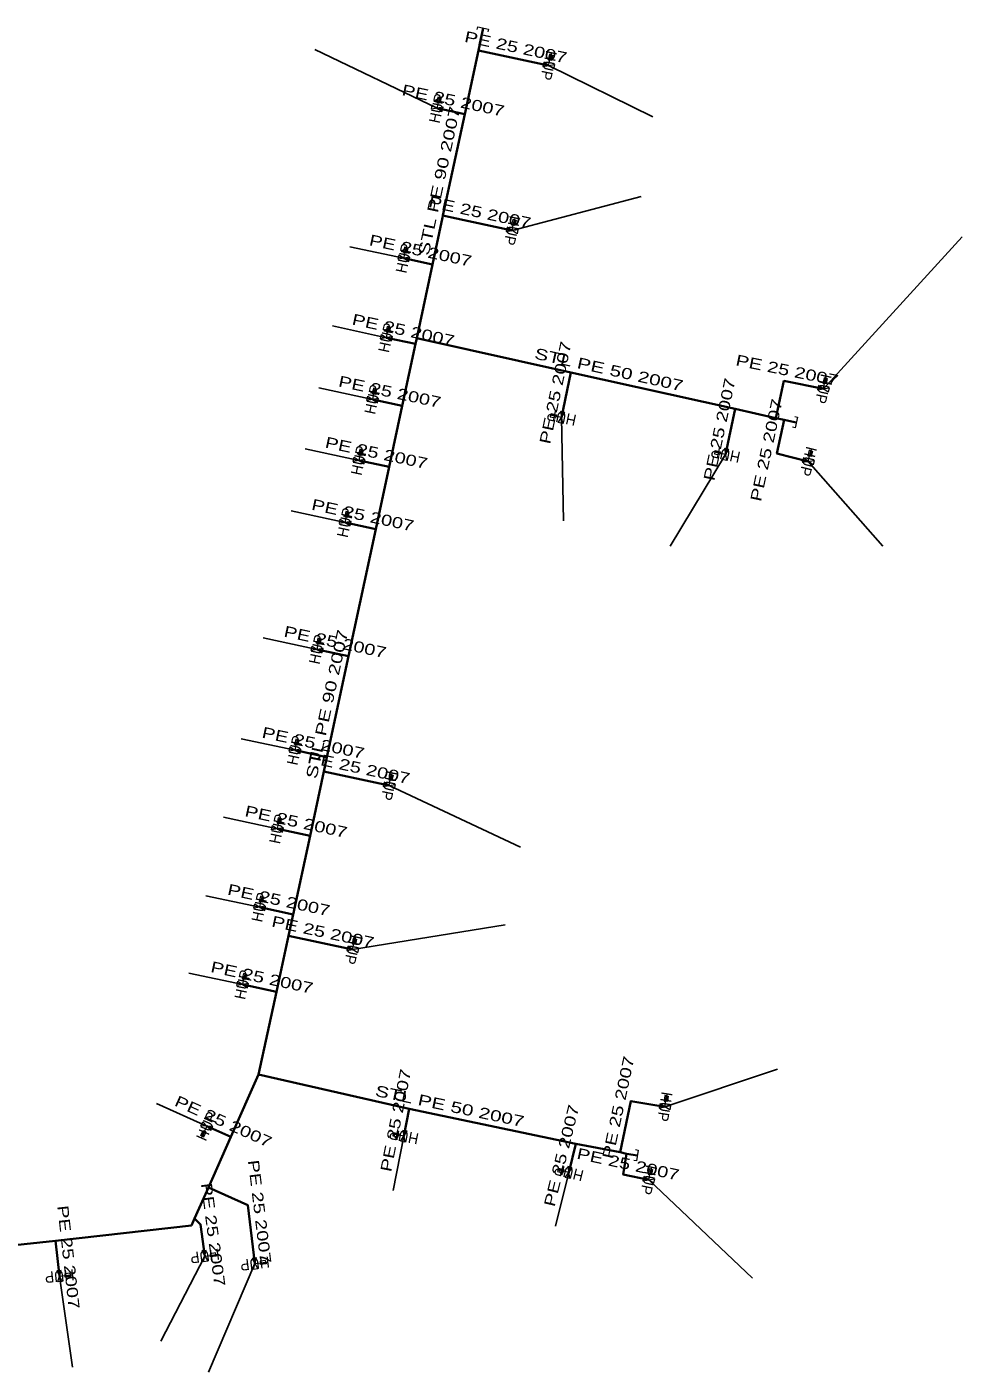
# Model space of a CAD drawing. Extents: x -737484 to -734496, y -1033882 to -1030666.
# Drawn here: x -735495.8 to -735411.1, y -1032104.6 to -1031982.7 of the extents above; entities that cross this region are included whole.
import ezdxf
from ezdxf.enums import TextEntityAlignment as Align

# ---------------------------------------------------------------- set-up
doc = ezdxf.new("R2010")
doc.units = 0
doc.header["$LTSCALE"] = 0.4
for name, color, linetype, lineweight in [('1', 7, 'Continuous', 13), ('22', 7, 'Continuous', 25), ('5', 7, 'Continuous', 35), ('7', 7, 'Continuous', 35)]:
    doc.layers.add(name, color=color, linetype=linetype, lineweight=lineweight)
doc.layers.add('2', color=7, linetype='Continuous')

msp = doc.modelspace()

# ---------------------------------------------------------------- linework, layer by layer
at = {"layer": '1'}
for p, q in [((-735448.387, -1031985.683), (-735448.314, -1031985.34)), ((-735448.58, -1031986.23), (-735448.476, -1031985.74)), ((-735458.477, -1031989.563), (-735458.404, -1031989.22)), ((-735458.67, -1031990.11), (-735458.566, -1031989.62)), ((-735451.89, -1032001.18), (-735451.786, -1032000.69)), ((-735451.697, -1032000.633), (-735451.624, -1032000.29)), ((-735461.68, -1032003.69), (-735461.576, -1032003.2)), ((-735461.487, -1032003.143), (-735461.414, -1032002.8)), ((-735463.26, -1032010.88), (-735463.156, -1032010.39)), ((-735463.067, -1032010.333), (-735462.994, -1032009.99)), ((-735423.517, -1032014.973), (-735423.444, -1032014.63)), ((-735464.51, -1032016.47), (-735464.406, -1032015.98)), ((-735464.317, -1032015.923), (-735464.244, -1032015.58)), ((-735423.71, -1032015.52), (-735423.606, -1032015.03)), ((-735447.966, -1032017.917), (-735448.309, -1032017.844)), ((-735447.42, -1032018.11), (-735447.909, -1032018.006)), ((-735465.74, -1032022), (-735465.636, -1032021.51)), ((-735465.547, -1032021.453), (-735465.474, -1032021.11)), ((-735433.116, -1032021.267), (-735433.459, -1032021.194)), ((-735432.57, -1032021.46), (-735433.059, -1032021.356)), ((-735425.08, -1032022.09), (-735424.959, -1032021.604)), ((-735424.868, -1032021.55), (-735424.783, -1032021.21)), ((-735466.807, -1032027.083), (-735466.734, -1032026.74)), ((-735467, -1032027.63), (-735466.896, -1032027.14)), ((-735469.54, -1032039.11), (-735469.436, -1032038.62)), ((-735469.347, -1032038.563), (-735469.274, -1032038.22)), ((-735471.347, -1032047.703), (-735471.274, -1032047.36)), ((-735471.54, -1032048.25), (-735471.436, -1032047.76)), ((-735463.02, -1032051.45), (-735462.916, -1032050.96)), ((-735462.827, -1032050.903), (-735462.754, -1032050.56)), ((-735473.13, -1032055.37), (-735473.026, -1032054.88)), ((-735472.937, -1032054.823), (-735472.864, -1032054.48)), ((-735474.74, -1032062.46), (-735474.636, -1032061.97)), ((-735474.547, -1032061.913), (-735474.474, -1032061.57)), ((-735466.33, -1032066.3), (-735466.226, -1032065.81)), ((-735466.137, -1032065.753), (-735466.064, -1032065.41)), ((-735476.28, -1032069.47), (-735476.176, -1032068.98)), ((-735476.087, -1032068.923), (-735476.014, -1032068.58)), ((-735438.06, -1032080.53), (-735437.981, -1032080.036)), ((-735437.895, -1032079.973), (-735437.841, -1032079.628)), ((-735479.832, -1032082.784), (-735479.974, -1032083.104)), ((-735479.53, -1032082.29), (-735479.733, -1032082.746)), ((-735462.24, -1032083.016), (-735462.583, -1032082.949)), ((-735461.69, -1032083.2), (-735462.18, -1032083.104)), ((-735447.299, -1032086.278), (-735447.639, -1032086.193)), ((-735446.76, -1032086.49), (-735447.245, -1032086.369)), ((-735439.52, -1032087.16), (-735439.416, -1032086.67)), ((-735439.327, -1032086.613), (-735439.254, -1032086.27)), ((-735479.71, -1032094.06), (-735479.214, -1032093.99)), ((-735479.13, -1032094.054), (-735478.783, -1032094.005)), ((-735475.18, -1032094.74), (-735474.683, -1032094.679)), ((-735474.6, -1032094.744), (-735474.252, -1032094.701)), ((-735492.87, -1032095.87), (-735492.372, -1032095.817)), ((-735492.29, -1032095.884), (-735491.942, -1032095.847))]:
    msp.add_line(p, q, dxfattribs=at)
for points in [[(-735455.051, -1031982.98), (-735454.999, -1031982.736), (-735454.02, -1031982.943), (-735454.072, -1031983.188)], [(-735426.3, -1032018.018), (-735426.056, -1032018.07), (-735426.263, -1032019.049), (-735426.508, -1032018.997)], [(-735440.718, -1032084.417), (-735440.471, -1032084.456), (-735440.628, -1032085.443), (-735440.875, -1032085.404)]]:
    msp.add_lwpolyline(points, dxfattribs=at)
for points in [[(-735448.372, -1031985.251), (-735448.518, -1031985.22), (-735448.622, -1031985.709), (-735448.476, -1031985.74)], [(-735448.372, -1031985.251), (-735448.225, -1031985.283), (-735448.329, -1031985.772), (-735448.476, -1031985.74)], [(-735448.343, -1031985.296), (-735448.27, -1031985.312), (-735448.358, -1031985.728), (-735448.432, -1031985.712)], [(-735448.049, -1031986.138), (-735448.132, -1031986.529), (-735449.027, -1031985.93), (-735449.11, -1031986.321)], [(-735458.462, -1031989.131), (-735458.608, -1031989.1), (-735458.712, -1031989.589), (-735458.566, -1031989.62)], [(-735458.462, -1031989.131), (-735458.315, -1031989.163), (-735458.419, -1031989.652), (-735458.566, -1031989.62)], [(-735458.433, -1031989.176), (-735458.36, -1031989.192), (-735458.448, -1031989.608), (-735458.522, -1031989.592)], [(-735459.2, -1031990.201), (-735459.117, -1031989.81), (-735458.222, -1031990.409), (-735458.139, -1031990.018)], [(-735451.682, -1032000.201), (-735451.828, -1032000.17), (-735451.932, -1032000.659), (-735451.786, -1032000.69)], [(-735451.682, -1032000.201), (-735451.535, -1032000.233), (-735451.639, -1032000.722), (-735451.786, -1032000.69)], [(-735451.359, -1032001.088), (-735451.442, -1032001.479), (-735452.337, -1032000.88), (-735452.42, -1032001.271)], [(-735451.653, -1032000.246), (-735451.58, -1032000.262), (-735451.668, -1032000.678), (-735451.742, -1032000.662)], [(-735462.21, -1032003.781), (-735462.127, -1032003.39), (-735461.232, -1032003.989), (-735461.149, -1032003.598)], [(-735461.472, -1032002.711), (-735461.618, -1032002.68), (-735461.722, -1032003.169), (-735461.576, -1032003.2)], [(-735461.472, -1032002.711), (-735461.325, -1032002.743), (-735461.429, -1032003.232), (-735461.576, -1032003.2)], [(-735461.443, -1032002.756), (-735461.37, -1032002.772), (-735461.458, -1032003.188), (-735461.532, -1032003.172)], [(-735463.052, -1032009.901), (-735463.198, -1032009.87), (-735463.302, -1032010.359), (-735463.156, -1032010.39)], [(-735463.052, -1032009.901), (-735462.905, -1032009.933), (-735463.009, -1032010.422), (-735463.156, -1032010.39)], [(-735463.023, -1032009.946), (-735462.95, -1032009.962), (-735463.038, -1032010.378), (-735463.112, -1032010.362)], [(-735463.79, -1032010.971), (-735463.707, -1032010.58), (-735462.812, -1032011.179), (-735462.729, -1032010.788)], [(-735423.502, -1032014.541), (-735423.648, -1032014.51), (-735423.752, -1032014.999), (-735423.606, -1032015.03)], [(-735423.502, -1032014.541), (-735423.355, -1032014.573), (-735423.459, -1032015.062), (-735423.606, -1032015.03)], [(-735423.473, -1032014.586), (-735423.4, -1032014.602), (-735423.488, -1032015.018), (-735423.562, -1032015.002)], [(-735464.302, -1032015.491), (-735464.448, -1032015.46), (-735464.552, -1032015.949), (-735464.406, -1032015.98)], [(-735464.302, -1032015.491), (-735464.155, -1032015.523), (-735464.259, -1032016.012), (-735464.406, -1032015.98)], [(-735464.273, -1032015.536), (-735464.2, -1032015.552), (-735464.288, -1032015.968), (-735464.362, -1032015.952)], [(-735423.179, -1032015.428), (-735423.262, -1032015.819), (-735424.157, -1032015.22), (-735424.24, -1032015.611)], [(-735465.04, -1032016.561), (-735464.957, -1032016.17), (-735464.062, -1032016.769), (-735463.979, -1032016.378)], [(-735448.398, -1032017.902), (-735448.429, -1032018.048), (-735447.94, -1032018.152), (-735447.909, -1032018.006)], [(-735448.398, -1032017.902), (-735448.366, -1032017.755), (-735447.877, -1032017.859), (-735447.909, -1032018.006)], [(-735448.353, -1032017.873), (-735448.337, -1032017.8), (-735447.921, -1032017.888), (-735447.937, -1032017.962)], [(-735447.328, -1032018.64), (-735447.719, -1032018.557), (-735447.12, -1032017.662), (-735447.511, -1032017.579)], [(-735432.478, -1032021.99), (-735432.869, -1032021.907), (-735432.27, -1032021.012), (-735432.661, -1032020.929)], [(-735466.27, -1032022.091), (-735466.187, -1032021.7), (-735465.292, -1032022.299), (-735465.209, -1032021.908)], [(-735465.532, -1032021.021), (-735465.678, -1032020.99), (-735465.782, -1032021.479), (-735465.636, -1032021.51)], [(-735465.532, -1032021.021), (-735465.385, -1032021.053), (-735465.489, -1032021.542), (-735465.636, -1032021.51)], [(-735465.503, -1032021.066), (-735465.43, -1032021.082), (-735465.518, -1032021.498), (-735465.592, -1032021.482)], [(-735433.548, -1032021.252), (-735433.579, -1032021.398), (-735433.09, -1032021.502), (-735433.059, -1032021.356)], [(-735433.548, -1032021.252), (-735433.516, -1032021.105), (-735433.027, -1032021.209), (-735433.059, -1032021.356)], [(-735433.503, -1032021.223), (-735433.487, -1032021.15), (-735433.071, -1032021.238), (-735433.087, -1032021.312)], [(-735424.546, -1032022.016), (-735424.643, -1032022.405), (-735425.516, -1032021.774), (-735425.613, -1032022.163)], [(-735424.838, -1032021.119), (-735424.983, -1032021.083), (-735425.104, -1032021.568), (-735424.959, -1032021.604)], [(-735424.838, -1032021.119), (-735424.692, -1032021.155), (-735424.813, -1032021.641), (-735424.959, -1032021.604)], [(-735424.811, -1032021.165), (-735424.738, -1032021.183), (-735424.841, -1032021.596), (-735424.914, -1032021.577)], [(-735466.792, -1032026.651), (-735466.938, -1032026.62), (-735467.042, -1032027.109), (-735466.896, -1032027.14)], [(-735466.792, -1032026.651), (-735466.645, -1032026.683), (-735466.749, -1032027.172), (-735466.896, -1032027.14)], [(-735466.763, -1032026.696), (-735466.69, -1032026.712), (-735466.778, -1032027.128), (-735466.852, -1032027.112)], [(-735467.53, -1032027.721), (-735467.447, -1032027.33), (-735466.552, -1032027.929), (-735466.469, -1032027.538)], [(-735470.07, -1032039.201), (-735469.987, -1032038.81), (-735469.092, -1032039.409), (-735469.009, -1032039.018)], [(-735469.332, -1032038.131), (-735469.478, -1032038.1), (-735469.582, -1032038.589), (-735469.436, -1032038.62)], [(-735469.332, -1032038.131), (-735469.185, -1032038.163), (-735469.289, -1032038.652), (-735469.436, -1032038.62)], [(-735469.303, -1032038.176), (-735469.23, -1032038.192), (-735469.318, -1032038.608), (-735469.392, -1032038.592)], [(-735471.332, -1032047.271), (-735471.478, -1032047.24), (-735471.582, -1032047.729), (-735471.436, -1032047.76)], [(-735471.332, -1032047.271), (-735471.185, -1032047.303), (-735471.289, -1032047.792), (-735471.436, -1032047.76)], [(-735471.303, -1032047.316), (-735471.23, -1032047.332), (-735471.318, -1032047.748), (-735471.392, -1032047.732)], [(-735472.07, -1032048.341), (-735471.987, -1032047.95), (-735471.092, -1032048.549), (-735471.009, -1032048.158)], [(-735462.489, -1032051.358), (-735462.572, -1032051.749), (-735463.467, -1032051.15), (-735463.55, -1032051.541)], [(-735462.812, -1032050.471), (-735462.958, -1032050.44), (-735463.062, -1032050.929), (-735462.916, -1032050.96)], [(-735462.812, -1032050.471), (-735462.665, -1032050.503), (-735462.769, -1032050.992), (-735462.916, -1032050.96)], [(-735462.783, -1032050.516), (-735462.71, -1032050.532), (-735462.798, -1032050.948), (-735462.872, -1032050.932)], [(-735472.922, -1032054.391), (-735473.068, -1032054.36), (-735473.172, -1032054.849), (-735473.026, -1032054.88)], [(-735472.922, -1032054.391), (-735472.775, -1032054.423), (-735472.879, -1032054.912), (-735473.026, -1032054.88)], [(-735472.893, -1032054.436), (-735472.82, -1032054.452), (-735472.908, -1032054.868), (-735472.982, -1032054.852)], [(-735473.66, -1032055.461), (-735473.577, -1032055.07), (-735472.682, -1032055.669), (-735472.599, -1032055.278)], [(-735475.27, -1032062.551), (-735475.187, -1032062.16), (-735474.292, -1032062.759), (-735474.209, -1032062.368)], [(-735474.532, -1032061.481), (-735474.678, -1032061.45), (-735474.782, -1032061.939), (-735474.636, -1032061.97)], [(-735474.532, -1032061.481), (-735474.385, -1032061.513), (-735474.489, -1032062.002), (-735474.636, -1032061.97)], [(-735474.503, -1032061.526), (-735474.43, -1032061.542), (-735474.518, -1032061.958), (-735474.592, -1032061.942)], [(-735465.799, -1032066.208), (-735465.882, -1032066.599), (-735466.777, -1032066), (-735466.86, -1032066.391)], [(-735466.122, -1032065.321), (-735466.268, -1032065.29), (-735466.372, -1032065.779), (-735466.226, -1032065.81)], [(-735466.122, -1032065.321), (-735465.975, -1032065.353), (-735466.079, -1032065.842), (-735466.226, -1032065.81)], [(-735466.093, -1032065.366), (-735466.02, -1032065.382), (-735466.108, -1032065.798), (-735466.182, -1032065.782)], [(-735476.81, -1032069.561), (-735476.727, -1032069.17), (-735475.832, -1032069.769), (-735475.749, -1032069.378)], [(-735476.072, -1032068.491), (-735476.218, -1032068.46), (-735476.322, -1032068.949), (-735476.176, -1032068.98)], [(-735476.072, -1032068.491), (-735475.925, -1032068.523), (-735476.029, -1032069.012), (-735476.176, -1032068.98)], [(-735476.043, -1032068.536), (-735475.97, -1032068.552), (-735476.058, -1032068.968), (-735476.132, -1032068.952)], [(-735437.534, -1032080.41), (-735437.597, -1032080.805), (-735438.522, -1032080.254), (-735438.585, -1032080.649)], [(-735437.903, -1032079.542), (-735438.051, -1032079.518), (-735438.129, -1032080.012), (-735437.981, -1032080.036)], [(-735437.903, -1032079.542), (-735437.755, -1032079.565), (-735437.833, -1032080.059), (-735437.981, -1032080.036)], [(-735437.872, -1032079.585), (-735437.798, -1032079.597), (-735437.865, -1032080.017), (-735437.939, -1032080.005)], [(-735479.936, -1032083.203), (-735480.073, -1032083.142), (-735479.87, -1032082.685), (-735479.733, -1032082.746)], [(-735480.068, -1032082.269), (-735479.905, -1032081.903), (-735479.154, -1032082.676), (-735478.991, -1032082.31)], [(-735479.955, -1032083.153), (-735480.023, -1032083.123), (-735479.85, -1032082.735), (-735479.782, -1032082.765)], [(-735479.936, -1032083.203), (-735479.799, -1032083.264), (-735479.596, -1032082.807), (-735479.733, -1032082.746)], [(-735462.671, -1032083.009), (-735462.7, -1032083.156), (-735462.209, -1032083.251), (-735462.18, -1032083.104)], [(-735462.671, -1032083.009), (-735462.643, -1032082.861), (-735462.152, -1032082.957), (-735462.18, -1032083.104)], [(-735462.627, -1032082.98), (-735462.612, -1032082.906), (-735462.195, -1032082.987), (-735462.21, -1032083.061)], [(-735461.589, -1032083.728), (-735461.981, -1032083.652), (-735461.398, -1032082.747), (-735461.79, -1032082.671)], [(-735447.73, -1032086.248), (-735447.766, -1032086.393), (-735447.281, -1032086.514), (-735447.245, -1032086.369)], [(-735447.73, -1032086.248), (-735447.694, -1032086.102), (-735447.208, -1032086.223), (-735447.245, -1032086.369)], [(-735447.684, -1032086.221), (-735447.666, -1032086.148), (-735447.253, -1032086.251), (-735447.272, -1032086.324)], [(-735446.686, -1032087.023), (-735447.075, -1032086.926), (-735446.444, -1032086.053), (-735446.833, -1032085.956)], [(-735439.312, -1032086.181), (-735439.458, -1032086.15), (-735439.562, -1032086.639), (-735439.416, -1032086.67)], [(-735439.312, -1032086.181), (-735439.165, -1032086.213), (-735439.269, -1032086.702), (-735439.416, -1032086.67)], [(-735439.283, -1032086.226), (-735439.21, -1032086.242), (-735439.298, -1032086.658), (-735439.372, -1032086.642)], [(-735438.989, -1032087.068), (-735439.072, -1032087.459), (-735439.967, -1032086.86), (-735440.05, -1032087.251)], [(-735479.442, -1032094.527), (-735479.838, -1032094.582), (-735479.581, -1032093.537), (-735479.977, -1032093.592)], [(-735478.719, -1032093.92), (-735478.74, -1032093.772), (-735479.235, -1032093.841), (-735479.214, -1032093.99)], [(-735478.719, -1032093.92), (-735478.698, -1032094.069), (-735479.193, -1032094.138), (-735479.214, -1032093.99)], [(-735478.752, -1032093.962), (-735478.741, -1032094.037), (-735479.162, -1032094.096), (-735479.173, -1032094.021)], [(-735474.92, -1032095.211), (-735475.317, -1032095.26), (-735475.042, -1032094.219), (-735475.439, -1032094.268)], [(-735474.187, -1032094.618), (-735474.205, -1032094.469), (-735474.702, -1032094.53), (-735474.683, -1032094.679)], [(-735474.187, -1032094.618), (-735474.169, -1032094.767), (-735474.665, -1032094.827), (-735474.683, -1032094.679)], [(-735474.22, -1032094.659), (-735474.211, -1032094.733), (-735474.633, -1032094.785), (-735474.642, -1032094.711)], [(-735492.618, -1032096.346), (-735493.016, -1032096.388), (-735492.723, -1032095.351), (-735493.121, -1032095.393)], [(-735491.875, -1032095.765), (-735491.891, -1032095.616), (-735492.388, -1032095.668), (-735492.372, -1032095.817)], [(-735491.875, -1032095.765), (-735491.859, -1032095.914), (-735492.357, -1032095.966), (-735492.372, -1032095.817)], [(-735491.909, -1032095.806), (-735491.901, -1032095.88), (-735492.324, -1032095.925), (-735492.332, -1032095.85)]]:
    msp.add_lwpolyline(points, close=True, dxfattribs=at)
at = {"layer": '22'}
for p, q in [((-735458.67, -1031990.11), (-735469.76, -1031984.772)), ((-735448.58, -1031986.23), (-735439.156, -1031990.889)), ((-735451.89, -1032001.18), (-735440.211, -1031998.101)), ((-735461.68, -1032003.69), (-735466.571, -1032002.651)), ((-735423.71, -1032015.52), (-735411.147, -1032001.753)), ((-735463.26, -1032010.88), (-735468.147, -1032009.821)), ((-735464.51, -1032016.47), (-735469.401, -1032015.43)), ((-735447.42, -1032018.11), (-735447.247, -1032027.476)), ((-735465.74, -1032022), (-735470.63, -1032020.957)), ((-735432.57, -1032021.46), (-735437.573, -1032029.763)), ((-735425.08, -1032022.09), (-735418.329, -1032029.757)), ((-735467, -1032027.63), (-735471.887, -1032026.572)), ((-735469.54, -1032039.11), (-735474.429, -1032038.064)), ((-735471.54, -1032048.25), (-735476.432, -1032047.217)), ((-735463.02, -1032051.45), (-735451.117, -1032057.027)), ((-735473.13, -1032055.37), (-735478.016, -1032054.31)), ((-735474.74, -1032062.46), (-735479.629, -1032061.415)), ((-735466.33, -1032066.3), (-735452.524, -1032064.063)), ((-735476.28, -1032069.47), (-735481.168, -1032068.419)), ((-735438.06, -1032080.53), (-735427.871, -1032077.12)), ((-735479.53, -1032082.29), (-735484.09, -1032080.24)), ((-735461.69, -1032083.2), (-735462.659, -1032088.105)), ((-735446.76, -1032086.49), (-735447.959, -1032091.344)), ((-735439.52, -1032087.16), (-735430.13, -1032096.042)), ((-735479.71, -1032094.06), (-735483.706, -1032101.756)), ((-735475.18, -1032094.74), (-735479.389, -1032104.562)), ((-735492.87, -1032095.87), (-735491.691, -1032104.13))]:
    msp.add_line(p, q, dxfattribs=at)
at = {"layer": '5'}
for points in [[(-735460.52, -1032010.94), (-735459.09, -1032004.24), (-735458.186, -1032000), (-735458.15, -1031999.83), (-735456.18, -1031990.64), (-735454.94, -1031984.87), (-735454.51, -1031982.84)], [(-735474.86, -1032077.61), (-735473.21, -1032070.13), (-735472.12, -1032065.06), (-735471.7, -1032063.11), (-735470.18, -1032056.01), (-735468.93, -1032050.18), (-735468.65, -1032048.86), (-735466.69, -1032039.72), (-735464.23, -1032028.23), (-735463.02, -1032022.58), (-735461.83, -1032017.04), (-735460.63, -1032011.45), (-735460.52, -1032010.94)], [(-735460.52, -1032010.94), (-735446.56, -1032014.03), (-735431.7, -1032017.33), (-735428, -1032018.17), (-735427.26, -1032018.32), (-735426.16, -1032018.56)], [(-735549.56, -1032088.85), (-735544.29, -1032089.97), (-735529.36, -1032093.16), (-735520.87, -1032094.93), (-735520.17, -1032095.11), (-735514.68, -1032094.87), (-735507.5, -1032094.15), (-735500.34, -1032093.43), (-735493.23, -1032092.66), (-735480.93, -1032091.29), (-735480.65, -1032090.65), (-735479.39, -1032087.84), (-735477.35, -1032083.27), (-735474.86, -1032077.61)], [(-735474.86, -1032077.61), (-735461.2, -1032080.72), (-735446.12, -1032083.9), (-735442.11, -1032084.63), (-735441.54, -1032084.8), (-735440.55, -1032084.95)]]:
    msp.add_lwpolyline(points, dxfattribs=at)
at = {"layer": '7'}
for p, q in [((-735454.94, -1031984.87), (-735448.58, -1031986.23)), ((-735456.18, -1031990.64), (-735458.67, -1031990.11)), ((-735459.09, -1032004.24), (-735461.68, -1032003.69)), ((-735460.63, -1032011.45), (-735463.26, -1032010.88)), ((-735446.56, -1032014.03), (-735447.42, -1032018.11)), ((-735461.83, -1032017.04), (-735464.51, -1032016.47)), ((-735431.7, -1032017.33), (-735432.57, -1032021.46)), ((-735463.02, -1032022.58), (-735465.74, -1032022)), ((-735464.23, -1032028.23), (-735467, -1032027.63)), ((-735466.69, -1032039.72), (-735469.54, -1032039.11)), ((-735468.65, -1032048.86), (-735471.54, -1032048.25)), ((-735468.93, -1032050.18), (-735463.02, -1032051.45)), ((-735470.18, -1032056.01), (-735473.13, -1032055.37)), ((-735471.7, -1032063.11), (-735474.74, -1032062.46)), ((-735472.12, -1032065.06), (-735466.33, -1032066.3)), ((-735473.21, -1032070.13), (-735476.28, -1032069.47)), ((-735461.2, -1032080.72), (-735461.69, -1032083.2)), ((-735477.35, -1032083.27), (-735479.53, -1032082.29)), ((-735446.12, -1032083.9), (-735446.76, -1032086.49)), ((-735493.23, -1032092.66), (-735492.87, -1032095.87))]:
    msp.add_line(p, q, dxfattribs=at)
for points in [[(-735458.15, -1031999.83), (-735457.361, -1032000), (-735451.89, -1032001.18)], [(-735428, -1032018.17), (-735427.28, -1032014.79), (-735423.71, -1032015.52)], [(-735427.26, -1032018.32), (-735427.91, -1032021.37), (-735425.08, -1032022.09)], [(-735442.11, -1032084.63), (-735441.13, -1032080.02), (-735438.06, -1032080.53)], [(-735441.54, -1032084.8), (-735441.83, -1032086.66), (-735439.52, -1032087.16)], [(-735479.39, -1032087.84), (-735475.83, -1032089.43), (-735475.18, -1032094.74)], [(-735480.65, -1032090.65), (-735480.09, -1032091.19), (-735479.71, -1032094.06)]]:
    msp.add_lwpolyline(points, dxfattribs=at)

# ---------------------------------------------------------------- texts
at = {"layer": '2', "width": 0.95}
for rotation, p in [(258, (-735449.0688, -1031986.1255)), (78, (-735458.1802, -1031990.2135)), (258, (-735452.3788, -1032001.0755)), (78, (-735461.1902, -1032003.7935)), (78, (-735462.7702, -1032010.9835)), (258, (-735424.1988, -1032015.4155)), (78, (-735464.0202, -1032016.5735)), (168, (-735447.3155, -1032017.6202)), (78, (-735465.2502, -1032022.1035)), (168, (-735432.4655, -1032020.9702)), (256, (-735425.565, -1032021.9685)), (78, (-735466.5102, -1032027.7335)), (78, (-735469.0502, -1032039.2135)), (78, (-735471.0502, -1032048.3535)), (258, (-735463.5088, -1032051.3455)), (78, (-735472.6402, -1032055.4735)), (78, (-735474.2502, -1032062.5635)), (258, (-735466.8188, -1032066.1955)), (78, (-735475.7902, -1032069.5735)), (261, (-735438.5535, -1032080.4513)), (66, (-735479.0723, -1032082.4929)), (169, (-735461.5941, -1032082.7089)), (166, (-735446.6385, -1032086.004)), (258, (-735440.0088, -1032087.0555)), (188, (-735479.7789, -1032093.5647)), (186, (-735492.9212, -1032095.3727)), (187, (-735475.2406, -1032094.2437))]:
    msp.add_text('HUP', height=1, rotation=rotation, dxfattribs=at).set_placement(p, align=Align.CENTER)
at = {"layer": '5', "width": 1.4}
for s, rotation, p in [('STL PE 90 2007', 77.901, (-735458.0083, -1031996.7838)), ('STL PE 50 2007', 347.479, (-735443.2299, -1032014.2566)), ('STL PE 90 2007', 77.897, (-735468.1558, -1032044.1748)), ('STL PE 50 2007', 348.092, (-735457.6357, -1032080.9596))]:
    msp.add_text(s, height=1, rotation=rotation, dxfattribs=at).set_placement(p, align=Align.CENTER)
at = {"layer": '7', "width": 1.35}
for rotation, p in [(347.93, (-735451.6551, -1031985.0605)), (347.984, (-735457.3201, -1031989.8851)), (347.829, (-735454.9139, -1032000.0158)), (348.011, (-735460.2809, -1032003.4758)), (347.771, (-735461.8389, -1032010.6755)), (78.097, (-735447.4792, -1032015.9661)), (348.443, (-735427.0872, -1032014.3184)), (347.993, (-735463.065, -1032016.2653)), (78.104, (-735432.6238, -1032019.2911)), (77.969, (-735428.3777, -1032021.1682)), (347.963, (-735464.2753, -1032021.8009)), (347.778, (-735465.5088, -1032027.4409)), (347.919, (-735468.0101, -1032038.9254)), (348.081, (-735469.9913, -1032048.0651)), (347.872, (-735465.8695, -1032050.3251)), (347.759, (-735471.5485, -1032055.2004)), (347.931, (-735473.115, -1032062.2954)), (347.912, (-735469.1197, -1032065.1909)), (347.867, (-735474.6391, -1032069.3107)), (77.999, (-735441.7851, -1032080.699)), (78.823, (-735461.9348, -1032081.8629)), (335.794, (-735478.2345, -1032082.3239)), (76.12, (-735446.9249, -1032085.0744)), (347.787, (-735441.4888, -1032086.2212)), (276.979, (-735475.2449, -1032090.0882)), (277.542, (-735479.4551, -1032092.1734)), (276.399, (-735492.5521, -1032094.2093))]:
    msp.add_text('PE 25 2007', height=1, rotation=rotation, dxfattribs=at).set_placement(p, align=Align.CENTER)

doc.saveas('drawing.dxf')
